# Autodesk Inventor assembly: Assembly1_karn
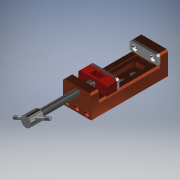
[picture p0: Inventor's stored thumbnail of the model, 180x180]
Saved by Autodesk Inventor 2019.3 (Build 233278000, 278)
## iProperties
Created: 2018-05
Part Number: Assembly1_karn
Document SubType Name: Assembly
Designer: Power User
Author: Power User
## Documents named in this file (7)
- D:\Karntarat T\06.MFG_Autodesk Inventor file\02.Training\INV01\INV-01 FILE\INV-01 Intro to Modeling\Vise\Assembly1_karn.iam
- D:\Karntarat T\06.MFG_Autodesk Inventor file\02.Training\INV01\INV-01 FILE\INV-01 Intro to Modeling\Vise\Body.ipt
- D:\Karntarat T\06.MFG_Autodesk Inventor file\02.Training\INV01\INV-01 FILE\INV-01 Intro to Modeling\Vise\FixedJaw.ipt
- D:\Karntarat T\06.MFG_Autodesk Inventor file\02.Training\INV01\INV-01 FILE\INV-01 Intro to Modeling\Vise\MovingJaw.ipt
- D:\Karntarat T\06.MFG_Autodesk Inventor file\02.Training\INV01\INV-01 FILE\INV-01 Intro to Modeling\Vise\Pin.ipt
- D:\Karntarat T\06.MFG_Autodesk Inventor file\02.Training\INV01\INV-01 FILE\INV-01 Intro to Modeling\Vise\Spindle.ipt
- C:\Users\Synergysoft\Documents\Inventor\Content Center Files\R2019\en-US\ISO 4762(2)\ISO 4762 - M5 x 8ISO.ipt
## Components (10 placed, 6 different names)
1. Body:1 — Mate:1, Insert:1, Insert:2, Mate:4, Mate:5, Angle:2
2. FixedJaw:1 — Mate:2, Mate:3, Insert:3, Moving
3. MovingJaw:1 — Mate:2, Mate:3, Insert:3, Mate:4, Flush:2, Angle:2, Rotation/Translation:1
4. Pin:1 — Mate:6, Mate:7
5. Spindle:1 — Mate:5, Mate:6, Mate:7, Flush:1, Rotation/Translation:1
6. FixedJaw:2 — Mate:1, Insert:1, Insert:2, Moving
7. ISO 4762 M5 x 8:1
8. ISO 4762 M5 x 8:2
9. ISO 4762 M5 x 8:3
10. ISO 4762 M5 x 8:4
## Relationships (15: Mate 8, Insert 3, Flush 2, Angle 1, RelateRotateTranslate 1)
- Mate:1: Body:1 ↔ FixedJaw:2
- Insert:1: Body:1 ↔ FixedJaw:2
- Insert:2: Body:1 ↔ FixedJaw:2
- Mate:2: FixedJaw:1 ↔ MovingJaw:1
- Mate:3: FixedJaw:1 ↔ MovingJaw:1
- Insert:3: FixedJaw:1 ↔ MovingJaw:1
- Mate:4: Body:1 ↔ MovingJaw:1
- Mate:5: Body:1 ↔ Spindle:1
- Mate:6: Pin:1 ↔ Spindle:1
- Mate:7: Pin:1 ↔ Spindle:1
- Flush:1: Spindle:1
- Flush:2: MovingJaw:1
- Moving [Mate]: FixedJaw:1 ↔ FixedJaw:2
- Angle:2: Body:1 ↔ MovingJaw:1
- Rotation/Translation:1 [RelateRotateTranslate]: MovingJaw:1 ↔ Spindle:1
